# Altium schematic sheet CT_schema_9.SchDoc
size 391 x 238 mm
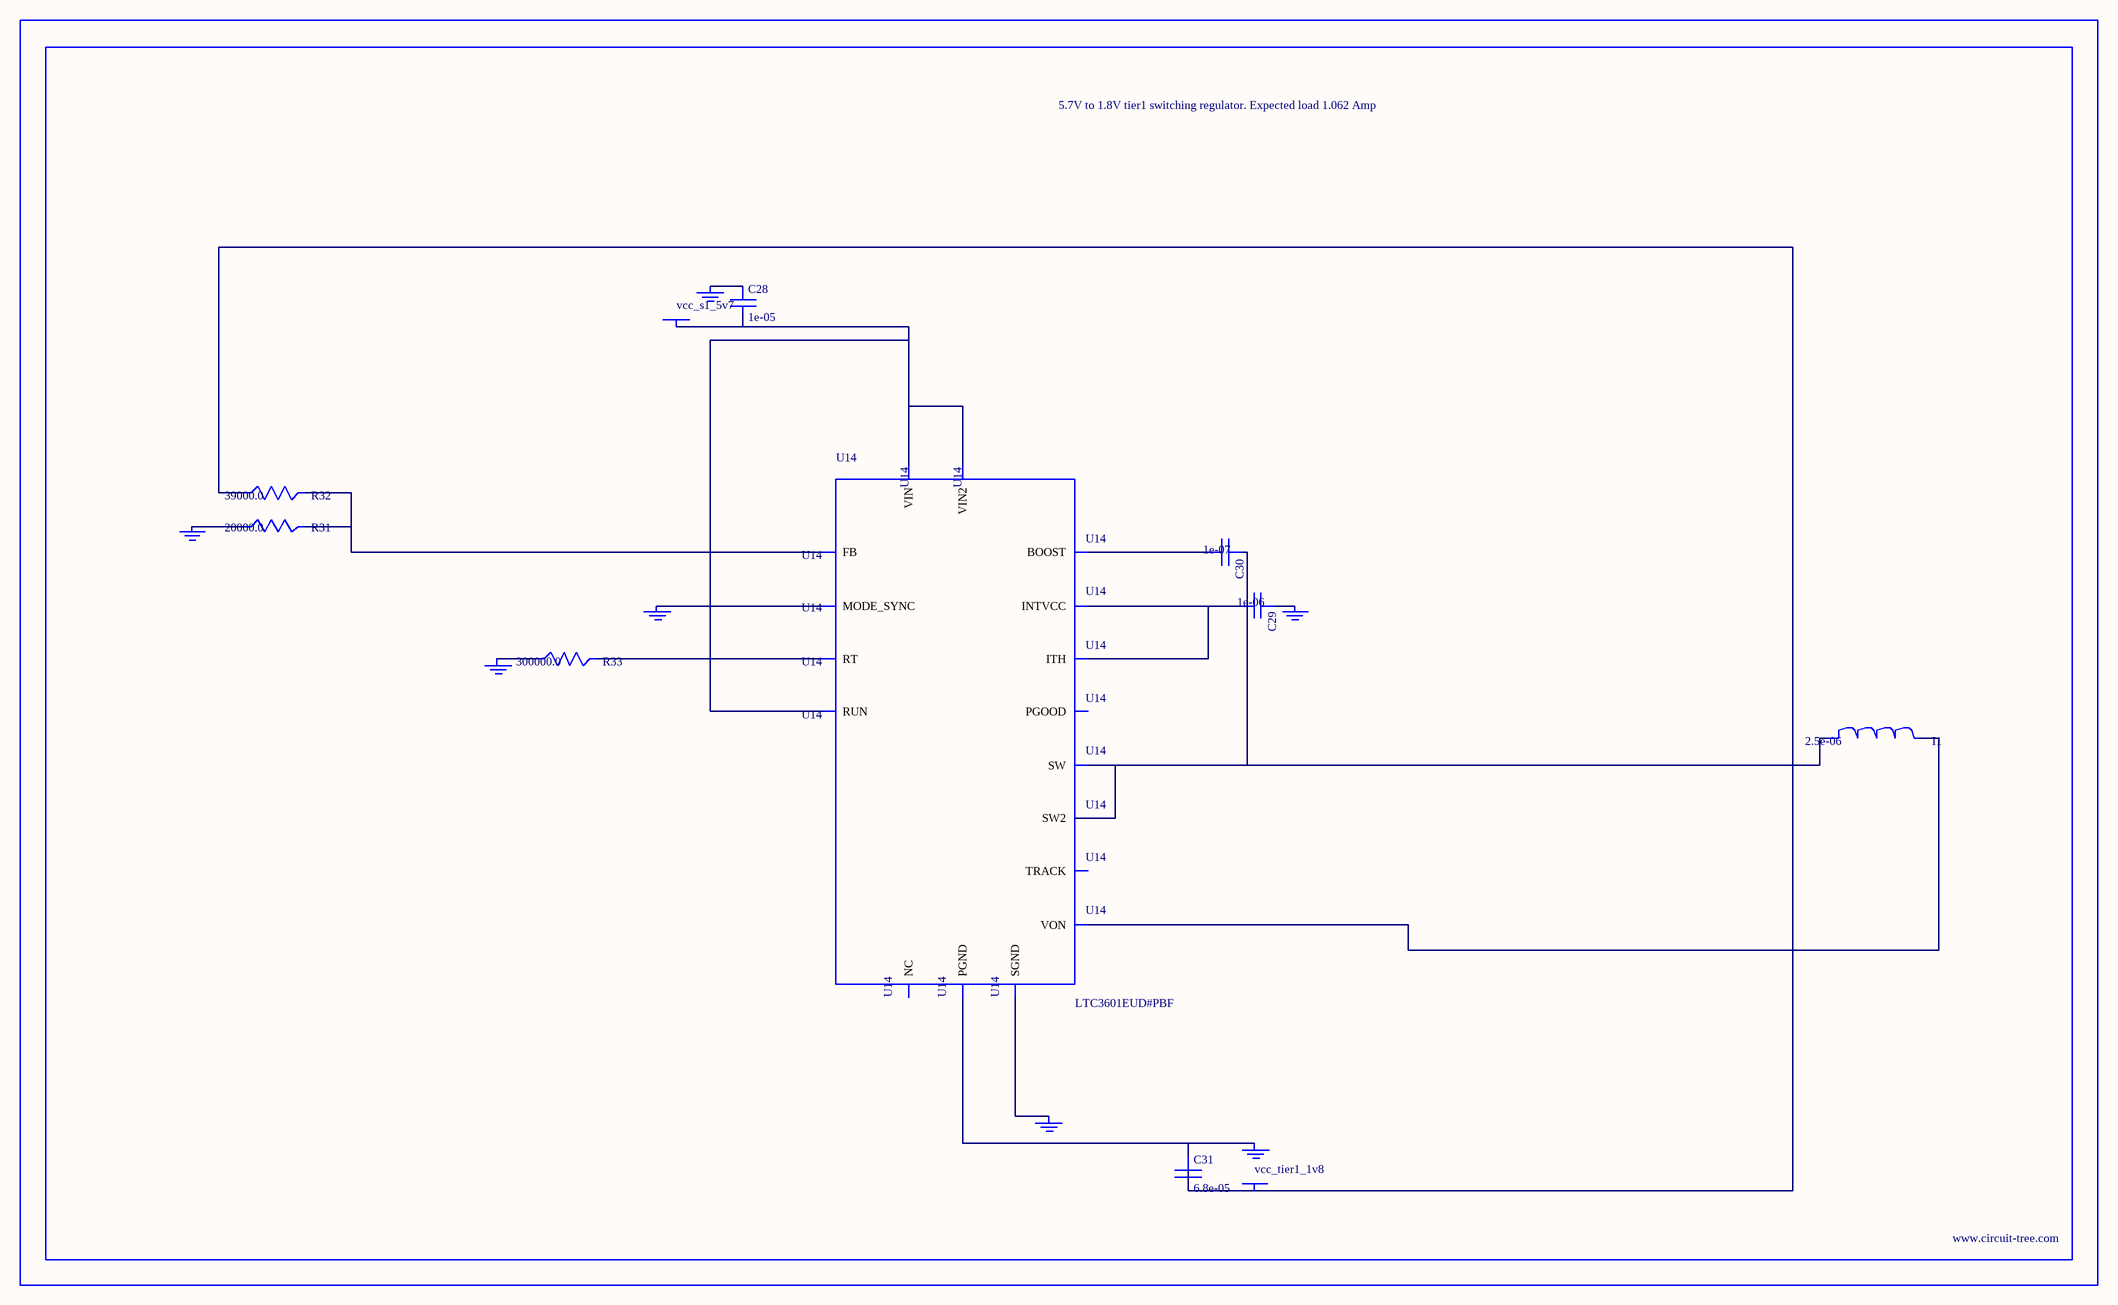
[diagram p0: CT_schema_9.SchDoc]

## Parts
BORDER8  (no value)
C28  1e-05  [C0805]
C29  1e-06  [C0603]
C30  1e-07  [C0402]
C31  6.8e-05  [2220]
GND_INSTANCE_8_0  (no value)
GND_INSTANCE_8_1  (no value)
GND_INSTANCE_8_2  (no value)
GND_INSTANCE_8_3  (no value)
GND_INSTANCE_8_4  (no value)
GND_INSTANCE_8_5  (no value)
GND_INSTANCE_8_6  (no value)
I1  2.5e-06  [DR1040]
POWER_INSTANCE_8_0  vcc_s1_5v7
POWER_INSTANCE_8_1  vcc_tier1_1v8
R31  20000.0  [R0603]
R32  39000.0  [R0603]
R33  300000.0  [R0603]
U14  LTC3601EUD#PBF  [QFN-16_EP]

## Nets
NetC28_1: C28.1 GND_INSTANCE_8_5.0(GND)
NetC28_2: C28.2 POWER_INSTANCE_8_0.0(PWR) U14.14(RUN) U14.15(VIN) U14.16(VIN2)
NetC29_1: C29.1 GND_INSTANCE_8_1.0(GND)
NetC29_2: C29.2 U14.7(INTVCC) U14.12(ITH)
NetC30_1: C30.1 I1.1 U14.3(SW) U14.4(SW2)
NetC30_2: C30.2 U14.6(BOOST)
NetC31_1: C31.1 GND_INSTANCE_8_6.0(GND) U14.17(PGND)
NetC31_2: C31.2 I1.2 POWER_INSTANCE_8_1.0(PWR) R32.1 U14.8(VON)
NetGND_INSTANCE_8_0_0: GND_INSTANCE_8_0.0(GND) U14.1(MODE_SYNC)
NetGND_INSTANCE_8_2_0: GND_INSTANCE_8_2.0(GND) U14.9(SGND)
NetGND_INSTANCE_8_3_0: GND_INSTANCE_8_3.0(GND) R33.1
NetGND_INSTANCE_8_4_0: GND_INSTANCE_8_4.0(GND) R31.1
NetR31_2: R31.2 R32.2 U14.11(FB)
NetR33_2: R33.2 U14.10(RT)

Not connected (* = marked no-connect by the designer): U14 2(PGOOD) 5(NC) 13(TRACK)

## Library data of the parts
BORDER8 = BORDER_PAGE8
C28 = C0805C106K8RACTU
C29 = C0603C105K3RACTU
C30 = C0402C104K3RACTU
C31 = C5750X5R1A686M
GND_INSTANCE_8_0-GND_INSTANCE_8_6 = GND
I1 = DR1040-2R5-R
POWER_INSTANCE_8_0 POWER_INSTANCE_8_1 = PWR
R31 = RC0603JR-0720KL
R32 = RC0603JR-0739KL
R33 = RC0603JR-07300KL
